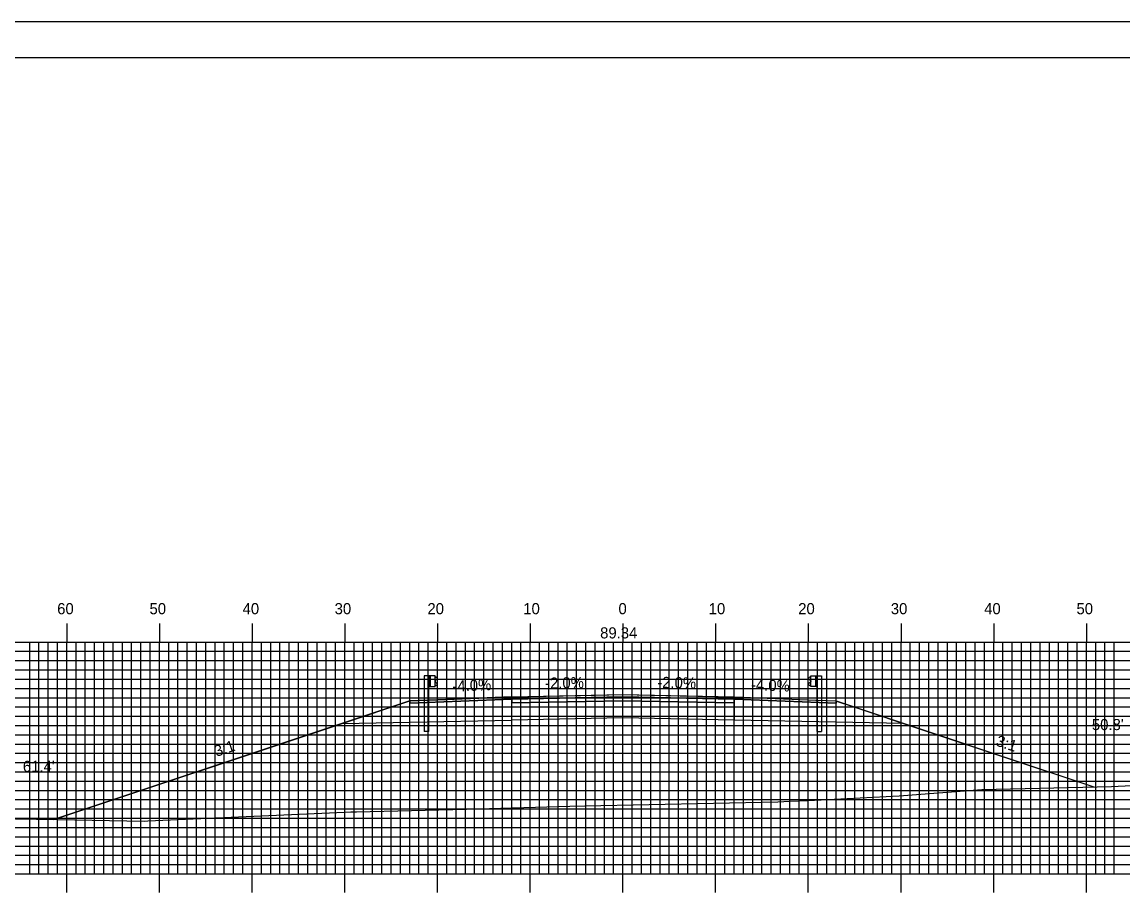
# Model space of a CAD drawing. Extents: x 1776744 to 1777088, y 442591 to 442811.
# Drawn here: x 1776845.4 to 1776964.2, y 442716.2 to 442810.5 of the extents above; entities that cross this region are included whole.
import ezdxf

# ---------------------------------------------------------------- set-up
doc = ezdxf.new("R2010")
doc.units = 0
for name, color, linetype in [('ANNOTATION', 7, 'Continuous'), ('BORDER', 7, 'Continuous'), ('D_Guardrail_Beam_Lt', 7, 'Continuous'), ('D_Guardrail_Beam_Rt', 7, 'Continuous'), ('D_Roadway_Centerline', 7, 'Continuous'), ('D_Roadway_Centerline_Text', 7, 'Continuous'), ('D_Roadway_Edge_Shoulder', 7, 'Continuous'), ('D_Roadway_Edge_TW', 7, 'Continuous'), ('D_Roadway_Pavement', 7, 'Continuous'), ('D_Roadway_SlopeLines', 7, 'Continuous'), ('D_Roadway_SubGrade', 7, 'Continuous'), ('D_Text_Standard', 7, 'Continuous'), ('H_V ANNOTATION', 7, 'Continuous'), ('MAJOR', 7, 'Continuous'), ('MINOR', 7, 'Continuous'), ('PLOT BOUNDARY', 7, 'Continuous'), ('S_Roadway_Centerline', 7, 'Continuous')]:
    doc.layers.add(name, color=color, linetype=linetype)

msp = doc.modelspace()

# ---------------------------------------------------------------- linework, layer by layer
at = {"layer": 'BORDER'}
msp.add_lwpolyline([(1776760.65, 442596.67), (1777080.65, 442596.67), (1777080.65, 442806.67), (1776760.65, 442806.67)], close=True, dxfattribs=at)
at = {"layer": 'D_Guardrail_Beam_Lt'}
for p, q in [((1776888.82, 442740.03), (1776888.82, 442734.03)), ((1776889.29, 442740.03), (1776888.82, 442740.03)), ((1776889.98, 442740.03), (1776889.29, 442740.03)), ((1776889.29, 442740.03), (1776889.29, 442738.86)), ((1776889.35, 442740.03), (1776889.35, 442738.86)), ((1776889.46, 442740.03), (1776889.46, 442738.86)), ((1776889.98, 442738.86), (1776889.98, 442740.03)), ((1776889.98, 442739.94), (1776890.05, 442739.93)), ((1776889.98, 442739.48), (1776889.98, 442739.41)), ((1776890.21, 442739.68), (1776890.02, 442739.54)), ((1776890.02, 442739.34), (1776890.21, 442739.21)), ((1776890.07, 442739.92), (1776890.21, 442739.82)), ((1776889.29, 442738.86), (1776889.98, 442738.86)), ((1776889.31, 442734.03), (1776889.31, 442738.86)), ((1776890.05, 442738.96), (1776889.98, 442738.94)), ((1776890.21, 442739.06), (1776890.07, 442738.96)), ((1776889.31, 442734.03), (1776888.82, 442734.03))]:
    msp.add_line(p, q, dxfattribs=at)
for centre, major_axis, start_param, end_param in [((1776890.06, 442739.48), (-0.0789, 0), 5.323254, 6.283185), ((1776890.06, 442739.41), (-0.0789, 0), 6.283185, 7.243116), ((1776890.05, 442739.89), (0.0417, 0), 0.959931, 1.376053), ((1776890.16, 442739.75), (0.0877, 0), 5.323254, 7.243116), ((1776890.05, 442739), (0.0417, 0), 4.907132, 5.323254), ((1776890.16, 442739.14), (0.0877, 0), 5.323254, 7.243116)]:
    msp.add_ellipse(centre, major_axis=major_axis, ratio=0.995501, start_param=start_param, end_param=end_param, dxfattribs=at)
at = {"layer": 'D_Guardrail_Beam_Rt'}
for p, q in [((1776930.43, 442739.92), (1776930.29, 442739.82)), ((1776930.29, 442739.68), (1776930.48, 442739.54)), ((1776930.48, 442739.34), (1776930.29, 442739.21)), ((1776930.52, 442739.94), (1776930.45, 442739.93)), ((1776930.52, 442740.03), (1776931.21, 442740.03)), ((1776930.52, 442738.86), (1776930.52, 442740.03)), ((1776930.52, 442739.48), (1776930.52, 442739.41)), ((1776931.04, 442740.03), (1776931.04, 442738.86)), ((1776931.15, 442740.03), (1776931.15, 442738.86)), ((1776931.21, 442740.03), (1776931.68, 442740.03)), ((1776931.21, 442740.03), (1776931.21, 442738.86)), ((1776931.68, 442740.03), (1776931.68, 442734.03)), ((1776930.29, 442739.06), (1776930.43, 442738.96)), ((1776930.45, 442738.96), (1776930.52, 442738.94)), ((1776931.21, 442738.86), (1776930.52, 442738.86)), ((1776931.19, 442734.03), (1776931.19, 442738.86)), ((1776931.19, 442734.03), (1776931.68, 442734.03))]:
    msp.add_line(p, q, dxfattribs=at)
for centre, major_axis, start_param, end_param in [((1776930.34, 442739.75), (-0.0877, 0), 5.323254, 7.243116), ((1776930.46, 442739.89), (-0.0417, 0), 4.907132, 5.323254), ((1776930.44, 442739.48), (0.0789, 0), 0, 0.959931), ((1776930.44, 442739.41), (0.0789, 0), 5.323254, 6.283185), ((1776930.34, 442739.14), (-0.0877, 0), 5.323254, 7.243116), ((1776930.46, 442739), (-0.0417, 0), 0.959931, 1.376053)]:
    msp.add_ellipse(centre, major_axis=major_axis, ratio=0.995501, start_param=start_param, end_param=end_param, dxfattribs=at)
at = {"layer": 'D_Roadway_Centerline'}
msp.add_lwpolyline([(1776848.86, 442724.52), (1776848.87, 442724.53), (1776879.97, 442734.9), (1776887.25, 442737.32), (1776890.25, 442737.44), (1776890.25, 442737.44), (1776898.25, 442737.76), (1776898.25, 442737.76), (1776905.68, 442737.91), (1776910.25, 442738), (1776916.42, 442737.88), (1776922.25, 442737.76), (1776922.25, 442737.76), (1776930.25, 442737.44), (1776931.06, 442737.41), (1776933.23, 442737.32), (1776933.25, 442737.32), (1776933.29, 442737.31), (1776936.58, 442736.21), (1776940.53, 442734.9), (1776951.43, 442731.26), (1776961.06, 442728.05)], dxfattribs=at)
at = {"layer": 'D_Roadway_Edge_Shoulder'}
for points in [[(1776898.25, 442737.76), (1776890.25, 442737.44), (1776890.25, 442737.44), (1776887.25, 442737.32), (1776887.25, 442737.07), (1776898.25, 442737.51)], [(1776922.25, 442737.76), (1776930.25, 442737.44), (1776930.25, 442737.44), (1776933.25, 442737.32), (1776933.25, 442737.07), (1776922.25, 442737.51)]]:
    msp.add_lwpolyline(points, close=True, dxfattribs=at)
at = {"layer": 'D_Roadway_Edge_TW'}
msp.add_lwpolyline([(1776898.25, 442737.51), (1776898.25, 442737.76), (1776910.25, 442738), (1776922.25, 442737.76), (1776922.25, 442737.51), (1776910.25, 442737.75)], close=True, dxfattribs=at)
at = {"layer": 'D_Roadway_Pavement'}
msp.add_lwpolyline([(1776898.25, 442737.1), (1776898.25, 442737.51), (1776910.25, 442737.75), (1776922.25, 442737.51), (1776922.25, 442737.1), (1776910.25, 442737.34)], close=True, dxfattribs=at)
for points in [[(1776898.25, 442737.51), (1776898.25, 442737.1)], [(1776922.25, 442737.51), (1776922.25, 442737.1)]]:
    msp.add_lwpolyline(points, dxfattribs=at)
at = {"layer": 'D_Roadway_SlopeLines'}
for points in [[(1776887.25, 442737.32), (1776848.86, 442724.52)], [(1776933.25, 442737.32), (1776961.06, 442728.05)]]:
    msp.add_lwpolyline(points, dxfattribs=at)
at = {"layer": 'D_Roadway_SubGrade'}
for points in [[(1776898.25, 442737.1), (1776898.25, 442737.51), (1776887.25, 442737.07), (1776887.25, 442737.32), (1776879.97, 442734.9), (1776898.25, 442735.26)], [(1776898.25, 442735.26), (1776898.25, 442737.51), (1776898.25, 442737.1), (1776910.25, 442737.34), (1776922.25, 442737.1), (1776922.25, 442737.51), (1776922.25, 442735.26), (1776910.25, 442735.5)], [(1776922.25, 442737.1), (1776922.25, 442737.51), (1776933.25, 442737.07), (1776933.25, 442737.32), (1776940.53, 442734.9), (1776922.25, 442735.26)]]:
    msp.add_lwpolyline(points, close=True, dxfattribs=at)
at = {"layer": 'MAJOR'}
for p, q in [((1776850.25, 442745.67), (1776850.25, 442743.67)), ((1776860.25, 442745.67), (1776860.25, 442743.67)), ((1776870.25, 442745.67), (1776870.25, 442743.67)), ((1776880.25, 442745.67), (1776880.25, 442743.67)), ((1776890.25, 442745.67), (1776890.25, 442743.67)), ((1776900.25, 442745.67), (1776900.25, 442743.67)), ((1776910.25, 442745.67), (1776910.25, 442743.67)), ((1776920.25, 442745.67), (1776920.25, 442743.67)), ((1776930.25, 442745.67), (1776930.25, 442743.67)), ((1776940.25, 442745.67), (1776940.25, 442743.67)), ((1776950.25, 442745.67), (1776950.25, 442743.67)), ((1776960.25, 442745.67), (1776960.25, 442743.67)), ((1776770.25, 442743.67), (1777050.25, 442743.67)), ((1776770.25, 442743.67), (1777050.25, 442743.67)), ((1776850.25, 442718.67), (1776850.25, 442743.67)), ((1776860.25, 442718.67), (1776860.25, 442743.67)), ((1776870.25, 442718.67), (1776870.25, 442743.67)), ((1776880.25, 442718.67), (1776880.25, 442743.67)), ((1776890.25, 442718.67), (1776890.25, 442743.67)), ((1776900.25, 442718.67), (1776900.25, 442743.67)), ((1776910.25, 442718.67), (1776910.25, 442743.67)), ((1776920.25, 442718.67), (1776920.25, 442743.67)), ((1776930.25, 442718.67), (1776930.25, 442743.67)), ((1776940.25, 442718.67), (1776940.25, 442743.67)), ((1776950.25, 442718.67), (1776950.25, 442743.67)), ((1776960.25, 442718.67), (1776960.25, 442743.67)), ((1776770.25, 442738.67), (1777050.25, 442738.67)), ((1776770.25, 442733.67), (1777050.25, 442733.67)), ((1776770.25, 442728.67), (1777050.25, 442728.67)), ((1776770.25, 442723.67), (1777050.25, 442723.67)), ((1776770.25, 442718.67), (1777050.25, 442718.67)), ((1776770.25, 442718.67), (1777050.25, 442718.67)), ((1776850.25, 442716.66), (1776850.25, 442718.67)), ((1776860.25, 442716.66), (1776860.25, 442718.67)), ((1776870.25, 442716.66), (1776870.25, 442718.67)), ((1776880.25, 442716.66), (1776880.25, 442718.67)), ((1776890.25, 442716.66), (1776890.25, 442718.67)), ((1776900.25, 442716.66), (1776900.25, 442718.67)), ((1776910.25, 442716.66), (1776910.25, 442718.67)), ((1776920.25, 442716.66), (1776920.25, 442718.67)), ((1776930.25, 442716.66), (1776930.25, 442718.67)), ((1776940.25, 442716.66), (1776940.25, 442718.67)), ((1776950.25, 442716.66), (1776950.25, 442718.67)), ((1776960.25, 442716.66), (1776960.25, 442718.67))]:
    msp.add_line(p, q, dxfattribs=at)
at = {"layer": 'MINOR'}
for p, q in [((1776846.25, 442718.67), (1776846.25, 442743.67)), ((1776847.25, 442718.67), (1776847.25, 442743.67)), ((1776848.25, 442718.67), (1776848.25, 442743.67)), ((1776849.25, 442718.67), (1776849.25, 442743.67)), ((1776851.25, 442718.67), (1776851.25, 442743.67)), ((1776852.25, 442718.67), (1776852.25, 442743.67)), ((1776853.25, 442718.67), (1776853.25, 442743.67)), ((1776854.25, 442718.67), (1776854.25, 442743.67)), ((1776855.25, 442718.67), (1776855.25, 442743.67)), ((1776856.25, 442718.67), (1776856.25, 442743.67)), ((1776857.25, 442718.67), (1776857.25, 442743.67)), ((1776858.25, 442718.67), (1776858.25, 442743.67)), ((1776859.25, 442718.67), (1776859.25, 442743.67)), ((1776861.25, 442718.67), (1776861.25, 442743.67)), ((1776862.25, 442718.67), (1776862.25, 442743.67)), ((1776863.25, 442718.67), (1776863.25, 442743.67)), ((1776864.25, 442718.67), (1776864.25, 442743.67)), ((1776865.25, 442718.67), (1776865.25, 442743.67)), ((1776866.25, 442718.67), (1776866.25, 442743.67)), ((1776867.25, 442718.67), (1776867.25, 442743.67)), ((1776868.25, 442718.67), (1776868.25, 442743.67)), ((1776869.25, 442718.67), (1776869.25, 442743.67)), ((1776871.25, 442718.67), (1776871.25, 442743.67)), ((1776872.25, 442718.67), (1776872.25, 442743.67)), ((1776873.25, 442718.67), (1776873.25, 442743.67)), ((1776874.25, 442718.67), (1776874.25, 442743.67)), ((1776875.25, 442718.67), (1776875.25, 442743.67)), ((1776876.25, 442718.67), (1776876.25, 442743.67)), ((1776877.25, 442718.67), (1776877.25, 442743.67)), ((1776878.25, 442718.67), (1776878.25, 442743.67)), ((1776879.25, 442718.67), (1776879.25, 442743.67)), ((1776881.25, 442718.67), (1776881.25, 442743.67)), ((1776882.25, 442718.67), (1776882.25, 442743.67)), ((1776883.25, 442718.67), (1776883.25, 442743.67)), ((1776884.25, 442718.67), (1776884.25, 442743.67)), ((1776885.25, 442718.67), (1776885.25, 442743.67)), ((1776886.25, 442718.67), (1776886.25, 442743.67)), ((1776887.25, 442718.67), (1776887.25, 442743.67)), ((1776888.25, 442718.67), (1776888.25, 442743.67)), ((1776889.25, 442718.67), (1776889.25, 442743.67)), ((1776891.25, 442718.67), (1776891.25, 442743.67)), ((1776892.25, 442718.67), (1776892.25, 442743.67)), ((1776893.25, 442718.67), (1776893.25, 442743.67)), ((1776894.25, 442718.67), (1776894.25, 442743.67)), ((1776895.25, 442718.67), (1776895.25, 442743.67)), ((1776896.25, 442718.67), (1776896.25, 442743.67)), ((1776897.25, 442718.67), (1776897.25, 442743.67)), ((1776898.25, 442718.67), (1776898.25, 442743.67)), ((1776899.25, 442718.67), (1776899.25, 442743.67)), ((1776901.25, 442718.67), (1776901.25, 442743.67)), ((1776902.25, 442718.67), (1776902.25, 442743.67)), ((1776903.25, 442718.67), (1776903.25, 442743.67)), ((1776904.25, 442718.67), (1776904.25, 442743.67)), ((1776905.25, 442718.67), (1776905.25, 442743.67)), ((1776906.25, 442718.67), (1776906.25, 442743.67)), ((1776907.25, 442718.67), (1776907.25, 442743.67)), ((1776908.25, 442718.67), (1776908.25, 442743.67)), ((1776909.25, 442718.67), (1776909.25, 442743.67)), ((1776911.25, 442718.67), (1776911.25, 442743.67)), ((1776912.25, 442718.67), (1776912.25, 442743.67)), ((1776913.25, 442718.67), (1776913.25, 442743.67)), ((1776914.25, 442718.67), (1776914.25, 442743.67)), ((1776915.25, 442718.67), (1776915.25, 442743.67)), ((1776916.25, 442718.67), (1776916.25, 442743.67)), ((1776917.25, 442718.67), (1776917.25, 442743.67)), ((1776918.25, 442718.67), (1776918.25, 442743.67)), ((1776919.25, 442718.67), (1776919.25, 442743.67)), ((1776921.25, 442718.67), (1776921.25, 442743.67)), ((1776922.25, 442718.67), (1776922.25, 442743.67)), ((1776923.25, 442718.67), (1776923.25, 442743.67)), ((1776924.25, 442718.67), (1776924.25, 442743.67)), ((1776925.25, 442718.67), (1776925.25, 442743.67)), ((1776926.25, 442718.67), (1776926.25, 442743.67)), ((1776927.25, 442718.67), (1776927.25, 442743.67)), ((1776928.25, 442718.67), (1776928.25, 442743.67)), ((1776929.25, 442718.67), (1776929.25, 442743.67)), ((1776931.25, 442718.67), (1776931.25, 442743.67)), ((1776932.25, 442718.67), (1776932.25, 442743.67)), ((1776933.25, 442718.67), (1776933.25, 442743.67)), ((1776934.25, 442718.67), (1776934.25, 442743.67)), ((1776935.25, 442718.67), (1776935.25, 442743.67)), ((1776936.25, 442718.67), (1776936.25, 442743.67)), ((1776937.25, 442718.67), (1776937.25, 442743.67)), ((1776938.25, 442718.67), (1776938.25, 442743.67)), ((1776939.25, 442718.67), (1776939.25, 442743.67)), ((1776941.25, 442718.67), (1776941.25, 442743.67)), ((1776942.25, 442718.67), (1776942.25, 442743.67)), ((1776943.25, 442718.67), (1776943.25, 442743.67)), ((1776944.25, 442718.67), (1776944.25, 442743.67)), ((1776945.25, 442718.67), (1776945.25, 442743.67)), ((1776946.25, 442718.67), (1776946.25, 442743.67)), ((1776947.25, 442718.67), (1776947.25, 442743.67)), ((1776948.25, 442718.67), (1776948.25, 442743.67)), ((1776949.25, 442718.67), (1776949.25, 442743.67)), ((1776951.25, 442718.67), (1776951.25, 442743.67)), ((1776952.25, 442718.67), (1776952.25, 442743.67)), ((1776953.25, 442718.67), (1776953.25, 442743.67)), ((1776954.25, 442718.67), (1776954.25, 442743.67)), ((1776955.25, 442718.67), (1776955.25, 442743.67)), ((1776956.25, 442718.67), (1776956.25, 442743.67)), ((1776957.25, 442718.67), (1776957.25, 442743.67)), ((1776958.25, 442718.67), (1776958.25, 442743.67)), ((1776959.25, 442718.67), (1776959.25, 442743.67)), ((1776961.25, 442718.67), (1776961.25, 442743.67)), ((1776962.25, 442718.67), (1776962.25, 442743.67)), ((1776963.25, 442718.67), (1776963.25, 442743.67)), ((1776770.25, 442742.67), (1777050.25, 442742.67)), ((1776770.25, 442741.67), (1777050.25, 442741.67)), ((1776770.25, 442740.67), (1777050.25, 442740.67)), ((1776770.25, 442739.67), (1777050.25, 442739.67)), ((1776770.25, 442737.67), (1777050.25, 442737.67)), ((1776770.25, 442736.67), (1777050.25, 442736.67)), ((1776770.25, 442735.67), (1777050.25, 442735.67)), ((1776770.25, 442734.67), (1777050.25, 442734.67)), ((1776770.25, 442732.67), (1777050.25, 442732.67)), ((1776770.25, 442731.67), (1777050.25, 442731.67)), ((1776770.25, 442730.67), (1777050.25, 442730.67)), ((1776770.25, 442729.67), (1777050.25, 442729.67)), ((1776770.25, 442727.67), (1777050.25, 442727.67)), ((1776770.25, 442726.67), (1777050.25, 442726.67)), ((1776770.25, 442725.67), (1777050.25, 442725.67)), ((1776770.25, 442724.67), (1777050.25, 442724.67)), ((1776770.25, 442722.67), (1777050.25, 442722.67)), ((1776770.25, 442721.67), (1777050.25, 442721.67)), ((1776770.25, 442720.67), (1777050.25, 442720.67)), ((1776770.25, 442719.67), (1777050.25, 442719.67))]:
    msp.add_line(p, q, dxfattribs=at)
at = {"layer": 'PLOT BOUNDARY'}
msp.add_lwpolyline([(1776744.46, 442590.55), (1777084.46, 442590.55), (1777084.46, 442810.55), (1776744.46, 442810.55)], close=True, dxfattribs=at)
at = {"layer": 'S_Roadway_Centerline'}
msp.add_lwpolyline([(1776835.65, 442724.75), (1776849.27, 442724.52), (1776858.6, 442724.36), (1776858.98, 442724.37), (1776880.22, 442725.31), (1776880.89, 442725.36), (1776881.51, 442725.36), (1776893.37, 442725.64), (1776904.51, 442725.95), (1776906.13, 442726), (1776926.96, 442726.44), (1776928.26, 442726.52), (1776930.25, 442726.58), (1776940.05, 442727.07), (1776948.95, 442727.76), (1776962.96, 442728.1), (1776972.5, 442728.57)], dxfattribs=at)

# ---------------------------------------------------------------- texts
at = {"layer": 'ANNOTATION'}
for s, rotation, p in [('-4.0%', 2.2905, (1776891.88, 442738.31)), ('-2.0%', 1.1458, (1776901.86, 442738.63)), ('-2.0%', 358.8542, (1776913.94, 442738.73)), ('-4.0%', 357.7095, (1776924.04, 442738.49)), ('3:1', 341.5666, (1776950.4, 442732.52)), ('3:1', 18.4357, (1776866.4, 442731.28))]:
    msp.add_text(s, height=1.2, rotation=rotation, dxfattribs=at).set_placement(p)
at = {"layer": 'D_Roadway_Centerline'}
for s, p in [('C', (1776910.25, 442738)), ('L', (1776910.25, 442737.99))]:
    msp.add_text(s, height=0.0146, dxfattribs=at).set_placement(p)
at = {"layer": 'D_Roadway_Centerline_Text'}
msp.add_text('89.34', height=1.2, dxfattribs=at).set_placement((1776907.79, 442744.06))
at = {"layer": 'D_Text_Standard'}
for s, p in [("50.8'", (1776960.84, 442734.17)), ("61.4'", (1776845.52, 442729.66))]:
    msp.add_text(s, height=1.2, dxfattribs=at).set_placement(p)
at = {"layer": 'H_V ANNOTATION'}
for s, p in [('60', (1776849.22, 442746.67)), ('50', (1776859.18, 442746.67)), ('40', (1776869.22, 442746.67)), ('30', (1776879.15, 442746.67)), ('20', (1776889.16, 442746.67)), ('10', (1776899.5, 442746.67)), ('0', (1776909.77, 442746.67)), ('10', (1776919.5, 442746.67)), ('20', (1776929.16, 442746.67)), ('30', (1776939.15, 442746.67)), ('40', (1776949.22, 442746.67)), ('50', (1776959.18, 442746.67))]:
    msp.add_text(s, height=1.2, dxfattribs=at).set_placement(p)

doc.saveas('drawing.dxf')
